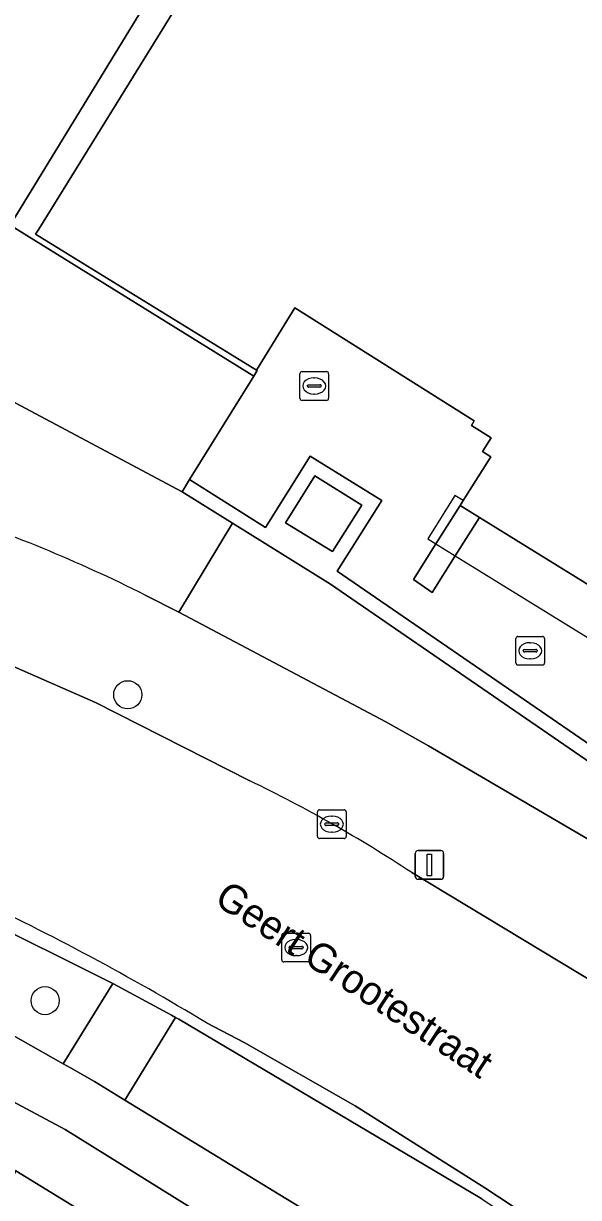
# Model space of a CAD drawing. Extents: x 162803 to 163818, y 381639 to 382475.
# Drawn here: x 162955.77 to 162975.11, y 382094.35 to 382135.2 of the extents above; entities that cross this region are included whole.
import ezdxf

# ---------------------------------------------------------------- set-up
doc = ezdxf.new("R2010")
doc.units = 0
for name, color, linetype in [('IMGEO_Boom', 7, 'Continuous'), ('IMGEO_Groenvoorziening', 7, 'Continuous'), ('IMGEO_Haag', 7, 'Continuous'), ('IMGEO_Kolk', 7, 'Continuous'), ('IMGEO_Lichtmast', 7, 'Continuous'), ('IMGEO_Muur', 7, 'Continuous'), ('IMGEO_Openbare_ruimte_label', 7, 'Continuous'), ('IMGEO_Pand', 7, 'Continuous'), ('IMGEO_Pand_overbouw', 7, 'Continuous'), ('IMGEO_Rijbaan_lokaal_gesloten', 7, 'Continuous'), ('IMGEO_Rioolput', 7, 'Continuous'), ('IMGEO_Voetpad_op_trap', 7, 'Continuous'), ('IMGEO_Voetpad_open', 7, 'Continuous')]:
    doc.layers.add(name, color=color, linetype=linetype)

msp = doc.modelspace()

# ---------------------------------------------------------------- linework, layer by layer
at = {"layer": 'IMGEO_Boom'}
for centre in [(162959.406, 382111.848), (162956.529, 382101.204)]:
    msp.add_circle(centre, 0.489, dxfattribs=at)
at = {"layer": 'IMGEO_Groenvoorziening'}
for points in [[(162964.687, 382143.52), (162965.112, 382144.206), (162965.949, 382145.559), (162965.6, 382145.775), (162965.505, 382145.621), (162964.052, 382146.289), (162957.563, 382150.357), (162956.76, 382149.06), (162943.979, 382128.415), (162949.687, 382125.09), (162961.296, 382118.907), (162961.56, 382119.332), (162963.795, 382122.934), (162955.309, 382128.186)], [(162964.9, 382117.831), (162966.542, 382116.829), (162967.56, 382118.447), (162965.918, 382119.461)], [(162963.057, 382117.813), (162961.188, 382114.725), (162968.395, 382110.901), (162969.88, 382110.073), (162975.42, 382106.84), (162977, 382105.878), (162977.447, 382105.592), (162978.561, 382107.397), (162966.462, 382115.698)]]:
    msp.add_lwpolyline(points, close=True, dxfattribs=at)
for points in [[(162960.01, 382115.318), (162961.188, 382114.725), (162963.057, 382117.813), (162961.296, 382118.907), (162949.687, 382125.09)], [(162944.68, 382105.243), (162948.601, 382103.625), (162952.721, 382101.507), (162957.157, 382099.01), (162958.885, 382101.806), (162954.037, 382104.216), (162953.795, 382104.36), (162953.553, 382104.503), (162946.305, 382107.347)], [(163000, 382064.141), (162988.306, 382072.452), (162975.64, 382081.142), (162964.013, 382088.892), (162957.595, 382092.972), (162957.972, 382093.775), (162955.509, 382095.286), (162955.095, 382094.405), (162947.756, 382098.312), (162942.304, 382100.629), (162935.833, 382102.859), (162935.503, 382103.431), (162934.025, 382103.793), (162930.797, 382104.582), (162926.669, 382103.516), (162926.014, 382103.347), (162923.417, 382102.535), (162923.386, 382102.523), (162920.985, 382101.569), (162918.543, 382100.297)], [(162966.225, 382091.127), (162957.229, 382096.722), (162949.64, 382100.771), (162943.839, 382103.472)], [(162971.736, 382094.304), (162961.188, 382100.561), (162961.071, 382100.624), (162959.31, 382097.746), (162967.324, 382092.842)], [(162955.06, 382095.576), (162955.509, 382095.286), (162957.972, 382093.775), (162966.406, 382088.6), (162979.279, 382080.171), (163010.771, 382057.59), (163010.938, 382058.34)]]:
    msp.add_lwpolyline(points, dxfattribs=at)
msp.add_arc((162936.425, 382068.315), 52.588, 63.3536, 71.9068, dxfattribs=at)
at = {"layer": 'IMGEO_Haag'}
for points in [[(162944.68, 382105.243), (162948.601, 382103.625), (162952.721, 382101.507), (162957.157, 382099.01), (162958.885, 382101.806), (162954.037, 382104.216), (162953.795, 382104.36), (162953.553, 382104.503), (162946.305, 382107.347)], [(162971.736, 382094.304), (162961.188, 382100.561), (162961.071, 382100.624), (162959.31, 382097.746), (162967.324, 382092.842)]]:
    msp.add_lwpolyline(points, dxfattribs=at)
at = {"layer": 'IMGEO_Kolk'}
for p, q in [((162965.476, 382123.092), (162966.328, 382123.092)), ((162965.401, 382122.166), (162965.401, 382123.018)), ((162965.889, 382122.872), (162965.914, 382122.872)), ((162966.402, 382123.018), (162966.402, 382122.166)), ((162965.66, 382122.586), (162965.66, 382122.598)), ((162966.098, 382122.549), (162965.7, 382122.549)), ((162965.703, 382122.635), (162966.101, 382122.635)), ((162965.912, 382122.312), (162965.887, 382122.312)), ((162966.144, 382122.598), (162966.144, 382122.586)), ((162966.328, 382122.092), (162965.476, 382122.092)), ((162972.921, 382112.953), (162972.921, 382113.805)), ((162972.996, 382113.879), (162973.848, 382113.879)), ((162973.922, 382113.805), (162973.922, 382112.953)), ((162973.18, 382113.373), (162973.18, 382113.385)), ((162973.618, 382113.336), (162973.22, 382113.336)), ((162973.223, 382113.422), (162973.621, 382113.422)), ((162973.409, 382113.659), (162973.434, 382113.659)), ((162973.664, 382113.385), (162973.664, 382113.373)), ((162973.848, 382112.879), (162972.996, 382112.879)), ((162973.432, 382113.099), (162973.407, 382113.099)), ((162966.012, 382106.92), (162966.012, 382107.772)), ((162966.087, 382107.846), (162966.939, 382107.846)), ((162966.5, 382107.626), (162966.525, 382107.626)), ((162967.013, 382107.772), (162967.013, 382106.92)), ((162966.271, 382107.34), (162966.271, 382107.352)), ((162966.709, 382107.303), (162966.311, 382107.303)), ((162966.314, 382107.389), (162966.712, 382107.389)), ((162966.755, 382107.352), (162966.755, 382107.34)), ((162966.939, 382106.846), (162966.087, 382106.846)), ((162966.523, 382107.066), (162966.498, 382107.066))]:
    msp.add_line(p, q, dxfattribs=at)
for points in [[(162965.476, 382123.092), (162966.328, 382123.092)], [(162965.401, 382122.166), (162965.401, 382123.018)], [(162966.402, 382123.018), (162966.402, 382122.166)], [(162966.328, 382122.092), (162965.476, 382122.092)], [(162972.921, 382112.953), (162972.921, 382113.805)], [(162972.996, 382113.879), (162973.848, 382113.879)], [(162973.922, 382113.805), (162973.922, 382112.953)], [(162973.848, 382112.879), (162972.996, 382112.879)], [(162966.012, 382106.92), (162966.012, 382107.772)], [(162966.087, 382107.846), (162966.939, 382107.846)], [(162967.013, 382107.772), (162967.013, 382106.92)], [(162966.939, 382106.846), (162966.087, 382106.846)]]:
    msp.add_lwpolyline(points, dxfattribs=at)
for centre, radius, start, end in [((162965.478, 382123.016), 0.0765, 91.552, 178.448), ((162965.478, 382123.016), 0.0765, 91.552, 178.448), ((162966.326, 382123.016), 0.0765, 1.552, 88.448), ((162966.326, 382123.016), 0.0765, 1.552, 88.448), ((162965.7, 382122.595), 0.0403, 85.8775, 175.7526), ((162965.697, 382122.585), 0.0366, 178.938, 274.7102), ((162966.101, 382122.592), 0.043, 264.8664, 352.4533), ((162966.105, 382122.597), 0.0386, 1.7309, 96.639), ((162965.478, 382122.168), 0.0765, 181.552, 268.448), ((162965.478, 382122.168), 0.0765, 181.552, 268.448), ((162966.326, 382122.168), 0.0765, 271.552, 358.448), ((162966.326, 382122.168), 0.0765, 271.552, 358.448), ((162972.998, 382113.803), 0.0765, 91.552, 178.448), ((162972.998, 382113.803), 0.0765, 91.552, 178.448), ((162973.846, 382113.803), 0.0765, 1.552, 88.448), ((162973.846, 382113.803), 0.0765, 1.552, 88.448), ((162973.22, 382113.382), 0.0403, 85.8775, 175.7526), ((162973.217, 382113.372), 0.0366, 178.938, 274.7102), ((162973.621, 382113.379), 0.043, 264.8664, 352.4533), ((162973.625, 382113.384), 0.0386, 1.7309, 96.639), ((162972.998, 382112.955), 0.0765, 181.552, 268.448), ((162972.998, 382112.955), 0.0765, 181.552, 268.448), ((162973.846, 382112.955), 0.0765, 271.552, 358.448), ((162973.846, 382112.955), 0.0765, 271.552, 358.448), ((162966.089, 382107.77), 0.0765, 91.552, 178.448), ((162966.089, 382107.77), 0.0765, 91.552, 178.448), ((162966.937, 382107.77), 0.0765, 1.552, 88.448), ((162966.937, 382107.77), 0.0765, 1.552, 88.448), ((162966.311, 382107.349), 0.0403, 85.8775, 175.7526), ((162966.308, 382107.339), 0.0366, 178.938, 274.7102), ((162966.712, 382107.346), 0.043, 264.8664, 352.4533), ((162966.716, 382107.351), 0.0386, 1.7309, 96.639), ((162966.089, 382106.922), 0.0765, 181.552, 268.448), ((162966.089, 382106.922), 0.0765, 181.552, 268.448), ((162966.937, 382106.922), 0.0765, 271.552, 358.448), ((162966.937, 382106.922), 0.0765, 271.552, 358.448)]:
    msp.add_arc(centre, radius, start, end, dxfattribs=at)
for centre, major_axis, ratio, start_param, end_param in [((162965.888, 382122.592), (-0.387, 0.002), 0.722429, 4.712389, 7.853982), ((162965.913, 382122.592), (-0.39, 0.002), 0.717154, 1.570796, 4.712389), ((162973.408, 382113.379), (-0.387, 0.002), 0.722429, 4.712389, 7.853982), ((162973.433, 382113.379), (-0.39, 0.002), 0.717154, 1.570796, 4.712389), ((162966.499, 382107.346), (-0.387, 0.002), 0.722429, 4.712389, 7.853982), ((162966.524, 382107.346), (-0.39, 0.002), 0.717154, 1.570796, 4.712389)]:
    msp.add_ellipse(centre, major_axis=major_axis, ratio=ratio, start_param=start_param, end_param=end_param, dxfattribs=at)
at = {"layer": 'IMGEO_Lichtmast'}
for p, q in [((162969.516, 382106.427), (162970.306, 382106.427)), ((162970.306, 382106.427), (162969.516, 382106.427)), ((162969.416, 382105.527), (162969.416, 382106.327)), ((162969.416, 382106.327), (162969.416, 382105.527)), ((162970.406, 382106.327), (162970.406, 382105.527)), ((162970.406, 382105.527), (162970.406, 382106.327)), ((162970.306, 382105.427), (162969.516, 382105.427)), ((162969.516, 382105.427), (162970.306, 382105.427))]:
    msp.add_line(p, q, dxfattribs=at)
msp.add_lwpolyline([(162969.836, 382106.302), (162969.986, 382106.302), (162969.986, 382105.552), (162969.836, 382105.552), (162969.836, 382106.302)], dxfattribs=at)
for centre, start, end in [((162969.516, 382106.327), 90, 180), ((162969.516, 382106.327), 90, 180), ((162970.306, 382106.327), 0, 90), ((162970.306, 382106.327), 360, 90), ((162969.516, 382105.527), 180, 270), ((162969.516, 382105.527), 180, 270), ((162970.306, 382105.527), 270, 0), ((162970.306, 382105.527), 270, 0)]:
    msp.add_arc(centre, 0.1, start, end, dxfattribs=at)
at = {"layer": 'IMGEO_Muur'}
for points in [[(162968.252, 382118.607), (162965.758, 382120.148), (162964.208, 382117.667), (162961.56, 382119.332), (162961.296, 382118.907), (162963.057, 382117.813), (162966.462, 382115.698), (162978.561, 382107.397), (162979.613, 382109.101), (162979.2, 382109.384), (162978.411, 382108.106), (162966.702, 382116.145)], [(162964.9, 382117.831), (162965.918, 382119.461), (162967.56, 382118.447), (162966.542, 382116.829)]]:
    msp.add_lwpolyline(points, close=True, dxfattribs=at)
at = {"layer": 'IMGEO_Pand'}
msp.add_lwpolyline([(162965.989, 382143.696), (162956.304, 382128.046), (162956.196, 382127.87), (162963.885, 382123.144), (162965.225, 382125.309), (162971.476, 382121.375), (162971.376, 382121.213), (162972.057, 382120.793), (162971.757, 382120.308), (162972.047, 382120.129), (162971.085, 382118.603), (162970.981, 382118.437), (162971.656, 382118.02), (162980.896, 382112.312)], dxfattribs=at)
at = {"layer": 'IMGEO_Pand_overbouw'}
msp.add_lwpolyline([(162970.981, 382118.437), (162971.085, 382118.603), (162970.792, 382118.783), (162969.858, 382117.268), (162970.136, 382117.096), (162970.813, 382116.679), (162980.376, 382110.787), (162983.099, 382115.166), (162982.796, 382115.386), (162980.896, 382112.312), (162971.656, 382118.02)], close=True, dxfattribs=at)
at = {"layer": 'IMGEO_Rijbaan_lokaal_gesloten'}
for points in [[(162963.662, 382108.852), (162958.288, 382111.581), (162952.764, 382113.993), (162942.065, 382117.986)], [(162977.029, 382101.004), (162969.294, 382105.661)], [(162962.144, 382100.432), (162963.466, 382099.749), (162967.331, 382097.547), (162971.846, 382094.694), (162978.168, 382090.53), (162980.505, 382088.959), (162983.831, 382086.727), (162988.435, 382083.403), (162994.327, 382079.209), (162996.195, 382077.928), (163000, 382075.218), (163011.231, 382067.05)]]:
    msp.add_lwpolyline(points, dxfattribs=at)
for centre, radius, start, end in [((162942.285, 382064.556), 49.185, 56.6918, 64.2379), ((162916.841, 382025.638), 87.444, 58.79685, 64.8929)]:
    msp.add_arc(centre, radius, start, end, dxfattribs=at)
at = {"layer": 'IMGEO_Rioolput'}
for p, q in [((162964.846, 382103.55), (162965.698, 382103.55)), ((162964.771, 382102.624), (162964.771, 382103.476)), ((162965.073, 382103.093), (162965.471, 382103.093)), ((162965.259, 382103.33), (162965.284, 382103.33)), ((162965.772, 382103.476), (162965.772, 382102.624)), ((162965.03, 382103.044), (162965.03, 382103.056)), ((162965.468, 382103.007), (162965.07, 382103.007)), ((162965.282, 382102.77), (162965.257, 382102.77)), ((162965.514, 382103.056), (162965.514, 382103.044)), ((162965.698, 382102.55), (162964.846, 382102.55))]:
    msp.add_line(p, q, dxfattribs=at)
for points in [[(162964.846, 382103.55), (162965.698, 382103.55)], [(162964.771, 382102.624), (162964.771, 382103.476)], [(162965.772, 382103.476), (162965.772, 382102.624)], [(162965.698, 382102.55), (162964.846, 382102.55)]]:
    msp.add_lwpolyline(points, dxfattribs=at)
for centre, radius, start, end in [((162964.848, 382103.474), 0.0765, 91.552, 178.448), ((162964.848, 382103.474), 0.0765, 91.552, 178.448), ((162965.696, 382103.474), 0.0765, 1.552, 88.448), ((162965.696, 382103.474), 0.0765, 1.552, 88.448), ((162965.07, 382103.053), 0.0403, 85.8775, 175.7526), ((162965.475, 382103.055), 0.0386, 1.7309, 96.639), ((162965.067, 382103.043), 0.0366, 178.938, 274.7102), ((162965.471, 382103.05), 0.043, 264.8664, 352.4533), ((162964.848, 382102.626), 0.0765, 181.552, 268.448), ((162964.848, 382102.626), 0.0765, 181.552, 268.448), ((162965.696, 382102.626), 0.0765, 271.552, 358.448), ((162965.696, 382102.626), 0.0765, 271.552, 358.448)]:
    msp.add_arc(centre, radius, start, end, dxfattribs=at)
for centre, major_axis, ratio, start_param, end_param in [((162965.258, 382103.05), (-0.387, 0.002), 0.722429, 4.712389, 7.853982), ((162965.283, 382103.05), (-0.39, 0.002), 0.717154, 1.570796, 4.712389)]:
    msp.add_ellipse(centre, major_axis=major_axis, ratio=ratio, start_param=start_param, end_param=end_param, dxfattribs=at)
at = {"layer": 'IMGEO_Voetpad_op_trap'}
msp.add_lwpolyline([(162971.656, 382118.02), (162970.981, 382118.437), (162970.136, 382117.096), (162969.354, 382115.855), (162970.011, 382115.404), (162970.813, 382116.679)], close=True, dxfattribs=at)
at = {"layer": 'IMGEO_Voetpad_open'}
for points in [[(162965.989, 382143.696), (162965.112, 382144.206), (162964.687, 382143.52), (162955.309, 382128.186), (162963.795, 382122.934), (162963.914, 382123.126), (162963.885, 382123.144), (162956.196, 382127.87), (162956.304, 382128.046)], [(162961.071, 382100.624), (162960.935, 382100.698), (162958.885, 382101.806), (162957.157, 382099.01), (162957.408, 382098.869), (162958.252, 382098.394), (162959.31, 382097.746)]]:
    msp.add_lwpolyline(points, close=True, dxfattribs=at)
for points in [[(162980.896, 382112.312), (162971.656, 382118.02), (162970.813, 382116.679), (162970.011, 382115.404), (162969.354, 382115.855), (162970.136, 382117.096), (162970.981, 382118.437), (162971.085, 382118.603), (162972.047, 382120.129), (162971.757, 382120.308), (162972.057, 382120.793), (162971.376, 382121.213), (162971.476, 382121.375), (162965.225, 382125.309), (162963.885, 382123.144), (162963.914, 382123.126), (162963.795, 382122.934), (162961.56, 382119.332), (162964.208, 382117.667), (162965.758, 382120.148), (162968.252, 382118.607), (162966.702, 382116.145), (162978.411, 382108.106)], [(162942.065, 382117.986), (162952.764, 382113.993), (162958.288, 382111.581), (162963.662, 382108.852)], [(163004.166, 382087.062), (163002.78, 382088.044), (163000, 382090.013), (162997.701, 382091.644), (162996.439, 382092.539), (162990.911, 382096.461), (162989.457, 382097.493), (162984.246, 382101.185), (162983.029, 382102.014), (162980.734, 382103.485), (162977.447, 382105.592), (162977, 382105.878), (162975.42, 382106.84), (162969.88, 382110.073), (162968.395, 382110.901), (162961.188, 382114.725), (162960.01, 382115.318)], [(162935.667, 382110.768), (162940.418, 382109.342), (162946.305, 382107.347), (162953.553, 382104.503), (162953.795, 382104.36), (162954.037, 382104.216), (162958.885, 382101.806), (162960.935, 382100.698), (162961.071, 382100.624), (162961.188, 382100.561), (162971.736, 382094.304), (162983.8, 382086.177), (163000, 382074.679), (163000.959, 382073.995), (163003.733, 382071.977)], [(162969.294, 382105.661), (162977.029, 382101.004)], [(162967.324, 382092.842), (162959.31, 382097.746), (162958.252, 382098.394), (162957.408, 382098.869), (162957.157, 382099.01), (162952.721, 382101.507), (162948.601, 382103.625), (162944.68, 382105.243)], [(162943.839, 382103.472), (162949.64, 382100.771), (162957.229, 382096.722), (162966.225, 382091.127)], [(163011.231, 382067.05), (163000, 382075.218), (162996.195, 382077.928), (162994.327, 382079.209), (162988.435, 382083.403), (162983.831, 382086.727), (162980.505, 382088.959), (162978.168, 382090.53), (162971.846, 382094.694), (162967.331, 382097.547), (162963.466, 382099.749), (162962.144, 382100.432)]]:
    msp.add_lwpolyline(points, dxfattribs=at)
for centre, radius, start, end in [((162936.425, 382068.315), 52.588, 63.3536, 71.9068), ((162942.285, 382064.556), 49.185, 56.6918, 64.2379), ((162916.841, 382025.638), 87.444, 58.79685, 64.8929)]:
    msp.add_arc(centre, radius, start, end, dxfattribs=at)

# ---------------------------------------------------------------- texts
at = {"layer": 'IMGEO_Openbare_ruimte_label'}
msp.add_text('Geert Grootestraat', height=1, rotation=326.6278, dxfattribs=at).set_placement((162962.372, 382104.599))

doc.saveas('drawing.dxf')
